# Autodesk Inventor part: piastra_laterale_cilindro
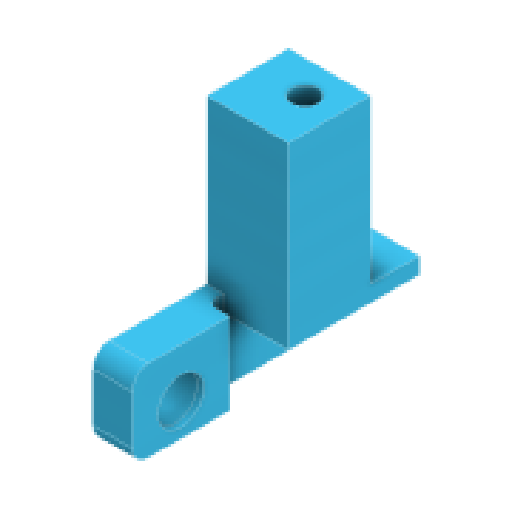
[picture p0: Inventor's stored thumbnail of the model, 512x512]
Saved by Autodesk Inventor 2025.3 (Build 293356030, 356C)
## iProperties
Created: 2025-09
Part Number: piastra_laterale_cilindro
Material: Plastica ABS
Document SubType Name: Modeling
Designer: R5800u
Density: 1.06 g/cm^3
Appearance: Liscia - Bianco
Author: R5800u
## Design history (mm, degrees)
sketch "Schizzo1"
  geometry: L1 (-2.5, 10)-(2.5, 10); L2 (2.5, 10)-(2.5, -10); L3 (2.5, -10)-(-2.5, -10); L4 (-2.5, -10)-(-2.5, 10); L5 (-2.5, 10)-(2.5, -10); L6 (2.5, 10)-(-2.5, -10); 1 further point
  constraints: 12 end point, 2 midpoint, 2 parallel, 1 horizontal, 1 perpendicular
  dimensions: "d0" = 5 distance of L2.end L3.end; "d1" = 20 distance of L1.end L2.end
extrude "Estrusione1" new body sketch "Schizzo1" stored distance "d2" = 50; taper "d3" = 0 deg
sketch "Schizzo2"
  geometry: L1 (50, 20)-(0, 20) reference; L2 (0, 0)-(25, 0); L3 (25, 0)-(25, 20); L4 (25, 20)-(0, 20); L5 (0, 20)-(0, 0); L6 (30, 1)-(30, 6.7) reference; L7 (25, 0)-(30, 0); L8 (30, 0)-(30, 20); L9 (30, 20)-(25, 20); L10 (25, 20)-(25, 0); 4 further points
  constraints: 16 end point, 4 parallel, 2 horizontal, 2 perpendicular, 1 midpoint, 1 point on line
  dimensions: "d4" = 20 distance of L3.end L2.end
extrude "Estrusione2" join sketch "Schizzo2" distance "d5" = 7; taper "d6" = 0 deg
sketch "Schizzo3"
  geometry: C1 r 4 at (-10, 10) reference; C2 r 8 at (-10, 10); 1 further point
  constraints: 1 centre point, 1 coincident
  dimensions: "d7" = 16 diameter of C2
extrude "Estrusione3" cut sketch "Schizzo3" extent not by distance; stored distance "d8" = 5; taper "d9" = 0 deg
sketch "Schizzo4"
  geometry: L1 (-2.5, -10)-(2.5, -10) reference; L2 (2.5, -10)-(2.5, 10) reference; L3 (2.5, 10)-(-2.5, 10) reference; L4 (-2.5, 10)-(-2.5, -10) reference; 1 further point
extrude "Estrusione4" join sketch "Schizzo4" distance "d10" = 20; taper "d11" = 0 deg
sketch "Schizzo5"
  geometry: L1 (0, 40)-(0, -5) reference; L2 (0, 0)-(20, 0); L3 (20, 0)-(20, 40); L4 (20, 40)-(0, 40); L5 (0, 40)-(0, 0); L6 (7, -5)-(7, -30) reference; L7 (0, 40)-(0, -5) reference; L8 (-5, 40)-(0, 40) reference; L9 (-5, 40)-(-5, -30) reference; L10 (0, 40)-(-5, 40); L11 (-5, -30)-(7, -30) reference; L12 (0, -5)-(7, -5) reference; 5 further points
  constraints: 10 end point, 2 parallel, 2 perpendicular, 1 horizontal, 1 point on line
  dimensions: "d13" = 20 distance of L4.end L3.end; "d14" = 40 distance of L3.end L2.end
extrude "Estrusione5" join sketch "Schizzo5" distance "d15" = 5; taper "d16" = 0 deg
sketch "Schizzo6"
  geometry: L1 (0, 40)-(0, 0) reference; 4 further points; 1 other entity
  constraints: 1 other
  dimensions: "d19" = 10 distance from line of L1 point (10, 15); "d20" = 25 dimension on point (10, 15)
hole "Foro1" sketch "Schizzo6" at (10, 15) diameter "d21" = 4.3; stored, may be unused: countersink angle "d25" = 90 deg, drill point angle "d27" = 118 deg; dims "d22" = 6, "d23" = 8, "d24" = 4.6, "d26" = 8
sketch "Schizzo7"
  geometry: L1 (0, 0)-(0, 20) reference; L2 (0, 10)-(25, 10); 3 further points
  constraints: 2 end point, 1 coincident, 1 horizontal, 1 midpoint, 1 point on line
  dimensions: "d28" = 25 distance of L2.start L2.end; "d29" = 10 distance from line of L1 point (10, 10)
hole "Foro2" sketch "Schizzo7" at (25, 10), (10, 10) diameter "d30" = 4.3; stored, may be unused: countersink angle "d34" = 90 deg, drill point angle "d36" = 118 deg; dims "d31" = 6, "d32" = 4, "d33" = 2, "d35" = 8
sketch "Schizzo8"
  geometry: L1 (-2.5, -10)-(9.5, -10) reference; L2 (9.5, -10)-(9.5, 15) reference; L3 (-2.5, 15)-(9.5, 15) reference; L4 (-2.5, -10)-(-2.5, 15) reference; 1 further point
extrude "Estrusione6" join sketch "Schizzo8" distance "d38" = 5; taper "d39" = 0 deg
fillet "Raccordo4" dims "d40" = 3
sketch "Schizzo9"
  geometry: L1 (0, 0)-(20, 0) reference; L2 (-5, 40)-(-5, -35) reference; L3 (20, 0)-(-5, 0); L4 (-5, 0)-(-5, 25); L5 (-5, 25)-(20, 25); L6 (20, 25)-(20, 0); C1 r 2.15 at (10, 15) reference; 3 further points
  constraints: 8 end point, 2 parallel, 1 horizontal, 1 perpendicular, 1 point on line
  dimensions: "d41" = 25 distance of L3.end L4.end
extrude "Estrusione7" join sketch "Schizzo9" distance "d42" = 50; taper "d43" = 0 deg
fillet "Raccordo5" dims "d44" = 5
sketch "Schizzo10"
  geometry: C1 r 2.15 at (10, 15) reference; 2 further points
  constraints: 1 coincident
hole "Foro3" sketch "Schizzo10" at (10, 15) diameter "d45" = 4.3; stored, may be unused: countersink angle "d49" = 90 deg, drill point angle "d51" = 118 deg; dims "d46" = 6, "d47" = 8, "d48" = 40, "d50" = 8
sketch "Schizzo11"
  geometry: C1 r 8 at (10, 10) reference; C2 r 7 at (10, 10); 1 further point
  constraints: 1 centre point, 1 coincident
  dimensions: "d52" = 14 diameter of C2
extrude "Estrusione8" join sketch "Schizzo11" distance "d53" = 2; taper "d54" = 0 deg
node "Solido1"
node "Riferimento1"
node "Riferimento2"
node "Linea chiusa proiettata1"
node "Linea chiusa proiettata2"
node "Linea chiusa proiettata3"
